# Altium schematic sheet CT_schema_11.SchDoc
size 391 x 238 mm
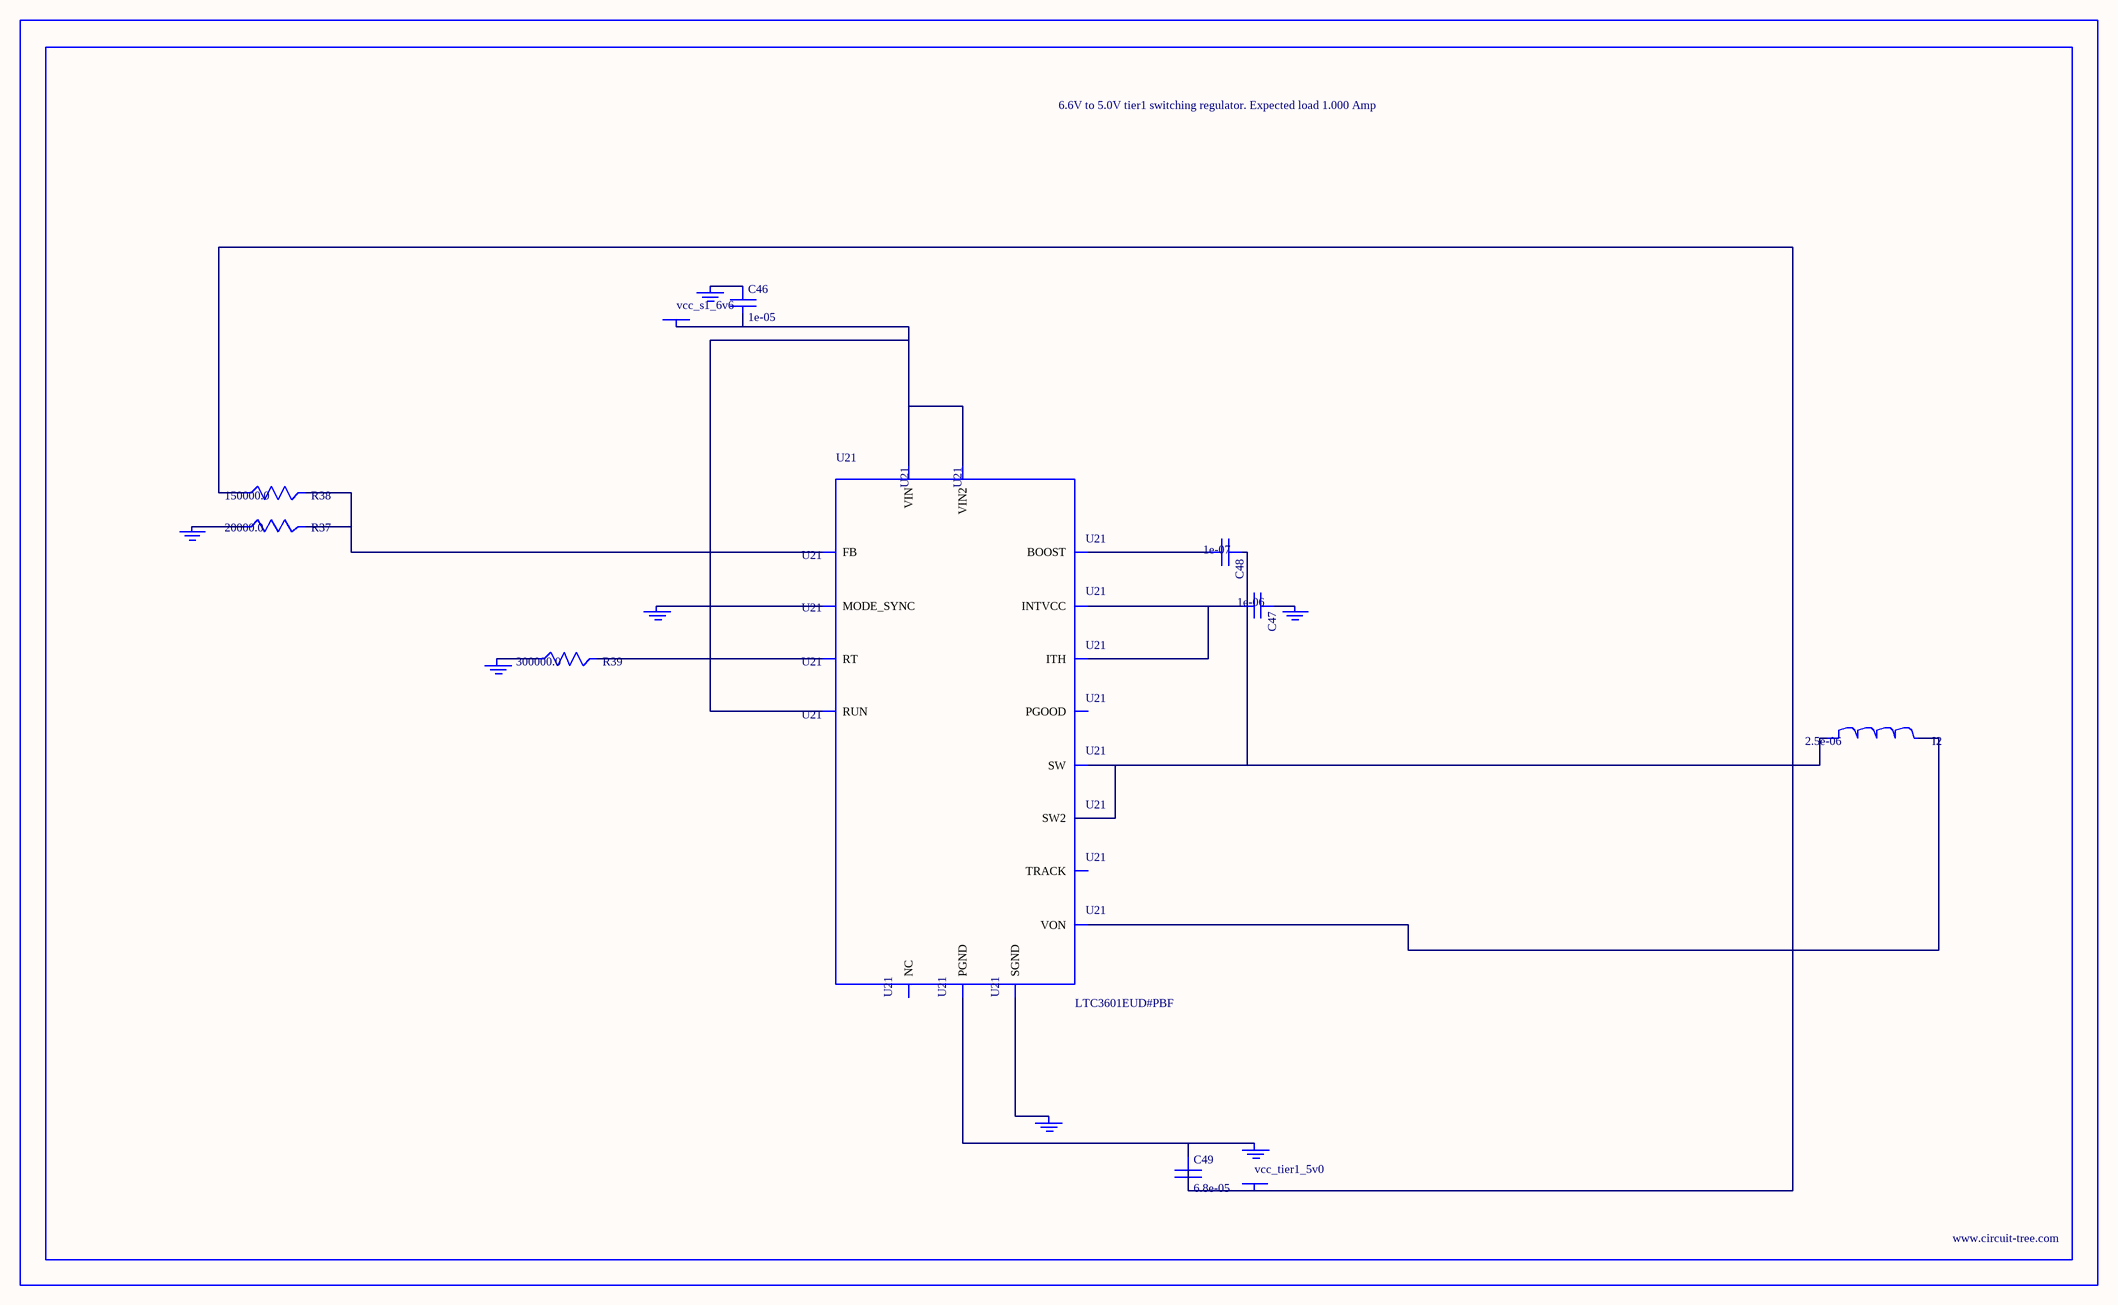
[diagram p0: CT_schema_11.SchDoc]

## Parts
BORDER10  (no value)
C46  1e-05  [C0805]
C47  1e-06  [C0603]
C48  1e-07  [C0402]
C49  6.8e-05  [2220]
GND_INSTANCE_10_0  (no value)
GND_INSTANCE_10_1  (no value)
GND_INSTANCE_10_2  (no value)
GND_INSTANCE_10_3  (no value)
GND_INSTANCE_10_4  (no value)
GND_INSTANCE_10_5  (no value)
GND_INSTANCE_10_6  (no value)
I2  2.5e-06  [DR1040]
POWER_INSTANCE_10_0  vcc_s1_6v6
POWER_INSTANCE_10_1  vcc_tier1_5v0
R37  20000.0  [R0603]
R38  150000.0  [R0603]
R39  300000.0  [R0603]
U21  LTC3601EUD#PBF  [QFN-16_EP]

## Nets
NetC46_1: C46.1 GND_INSTANCE_10_5.0(GND)
NetC46_2: C46.2 POWER_INSTANCE_10_0.0(PWR) U21.14(RUN) U21.15(VIN) U21.16(VIN2)
NetC47_1: C47.1 GND_INSTANCE_10_1.0(GND)
NetC47_2: C47.2 U21.7(INTVCC) U21.12(ITH)
NetC48_1: C48.1 I2.1 U21.3(SW) U21.4(SW2)
NetC48_2: C48.2 U21.6(BOOST)
NetC49_1: C49.1 GND_INSTANCE_10_6.0(GND) U21.17(PGND)
NetC49_2: C49.2 I2.2 POWER_INSTANCE_10_1.0(PWR) R38.1 U21.8(VON)
NetGND_INSTANCE_10_0_0: GND_INSTANCE_10_0.0(GND) U21.1(MODE_SYNC)
NetGND_INSTANCE_10_2_0: GND_INSTANCE_10_2.0(GND) U21.9(SGND)
NetGND_INSTANCE_10_3_0: GND_INSTANCE_10_3.0(GND) R39.1
NetGND_INSTANCE_10_4_0: GND_INSTANCE_10_4.0(GND) R37.1
NetR37_2: R37.2 R38.2 U21.11(FB)
NetR39_2: R39.2 U21.10(RT)

Not connected (* = marked no-connect by the designer): U21 2(PGOOD) 5(NC) 13(TRACK)

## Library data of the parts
BORDER10 = BORDER_PAGE10
C46 = C0805C106K8RACTU
C47 = C0603C105K3RACTU
C48 = C0402C104K3RACTU
C49 = C5750X5R1A686M
GND_INSTANCE_10_0-GND_INSTANCE_10_6 = GND
I2 = DR1040-2R5-R
POWER_INSTANCE_10_0 POWER_INSTANCE_10_1 = PWR
R37 = RC0603JR-0720KL
R38 = RC0603JR-07150KL
R39 = RC0603JR-07300KL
